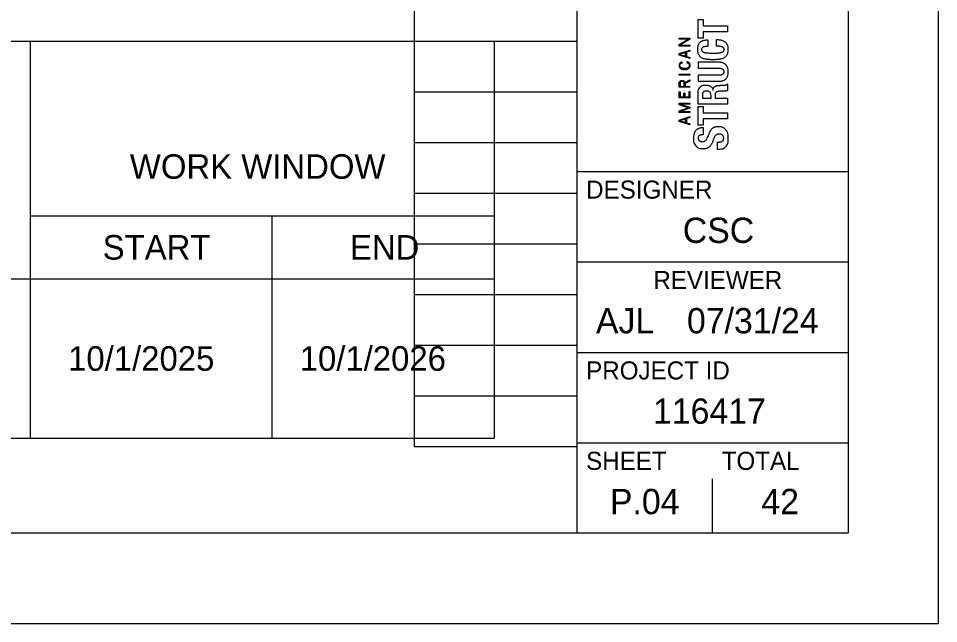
# Model space of a CAD drawing. Extents: x 0 to 84.3, y -13.4 to 22.
# Drawn here: x 28.91 to 34, y 0 to 3.35 of the extents above; entities that cross this region are included whole.
import ezdxf

# ---------------------------------------------------------------- set-up
doc = ezdxf.new("R2010")
doc.units = 0
for name, color, linetype in [('SH_Border', 7, 'Continuous'), ('SH_Cut_Line', 7, 'Continuous'), ('SH_Data', 7, 'Continuous'), ('SH_Text', 7, 'Continuous')]:
    doc.layers.add(name, color=color, linetype=linetype)

msp = doc.modelspace()

# ---------------------------------------------------------------- linework, layer by layer
at = {"layer": 'SH_Border'}
for p, q in [((32, 0.5), (32, 21.5)), ((32, 2.5), (33.5, 2.5)), ((32, 2), (33.5, 2)), ((32, 1.5), (33.5, 1.5)), ((32, 1), (33.5, 1))]:
    msp.add_line(p, q, dxfattribs=at)
msp.add_lwpolyline([(1.5, 21.5), (33.5, 21.5), (33.5, 0.5), (1.5, 0.5)], close=True, dxfattribs=at)
at = {"layer": 'SH_Cut_Line'}
msp.add_lwpolyline([(0, 0), (34, 0), (34, 22), (0, 22)], close=True, dxfattribs=at)
at = {"layer": 'SH_Data'}
for p, q in [((31.1, 0.98), (31.1, 21.14)), ((32, 0.98), (32, 21.14)), ((31.1, 3.22), (32, 3.22)), ((31.1, 2.94), (32, 2.94)), ((31.1, 2.66), (32, 2.66)), ((31.1, 2.38), (32, 2.38)), ((31.1, 2.1), (32, 2.1)), ((31.1, 1.82), (32, 1.82)), ((31.1, 1.54), (32, 1.54)), ((31.1, 1.26), (32, 1.26)), ((31.1, 0.98), (32, 0.98)), ((32.75, 0.5), (32.75, 0.8)), ((32.375, 0.675), (32.375, 0.675))]:
    msp.add_line(p, q, dxfattribs=at)
for points in [[(32.6696, 3.3411), (32.6967, 3.3411), (32.6967, 3.3054), (32.8329, 3.3054), (32.8329, 3.2726), (32.6967, 3.2726), (32.6967, 3.2369), (32.6696, 3.2369), (32.6696, 3.3411)], [(32.565, 3.1938), (32.565, 3.2029), (32.6146, 3.2313), (32.6146, 3.2315), (32.565, 3.2315), (32.565, 3.2369), (32.6245, 3.2369), (32.6245, 3.2313), (32.5694, 3.1994), (32.5694, 3.1992), (32.6245, 3.1992), (32.6245, 3.1938), (32.565, 3.1938)], [(32.6245, 3.1249), (32.565, 3.1439), (32.565, 3.1523), (32.6245, 3.1711), (32.6245, 3.1653), (32.605, 3.1593), (32.605, 3.1368), (32.6245, 3.1307), (32.6245, 3.1249)], [(32.6006, 3.1382), (32.6006, 3.158), (32.5694, 3.1481), (32.5694, 3.148), (32.6006, 3.1382)], [(32.565, 3.0336), (32.565, 3.039), (32.6245, 3.039), (32.6245, 3.0336), (32.565, 3.0336)], [(32.5963, 2.9917), (32.6245, 3.0063), (32.6245, 3.0004), (32.5973, 2.9865), (32.5973, 2.9711), (32.6245, 2.9711), (32.6245, 2.9656), (32.565, 2.9656), (32.565, 2.9858)], [(32.5694, 2.9711), (32.5928, 2.9711), (32.5928, 2.9858)], [(32.5694, 2.9858), (32.5694, 2.9711)], [(32.8316, 2.9843), (32.8329, 2.9843), (32.8329, 2.9486)], [(32.6245, 2.9074), (32.565, 2.9074), (32.565, 2.9414), (32.5694, 2.9414), (32.5694, 2.9129), (32.5913, 2.9129), (32.5913, 2.9334), (32.5958, 2.9334), (32.5958, 2.9129), (32.62, 2.9129), (32.62, 2.943), (32.6245, 2.943), (32.6245, 2.9074)], [(32.8329, 2.8731), (32.6696, 2.8731), (32.6696, 2.9341)], [(32.694, 2.9217), (32.694, 2.9059)], [(32.694, 2.9059), (32.7409, 2.9059), (32.7409, 2.9198)], [(32.7519, 2.9506), (32.7524, 2.9506)], [(32.7638, 2.9238), (32.7638, 2.9059), (32.8329, 2.9059), (32.8329, 2.8731)], [(32.8158, 2.9445), (32.7844, 2.9435)], [(32.6245, 2.8264), (32.565, 2.8264), (32.565, 2.836), (32.6154, 2.8524), (32.6154, 2.8526), (32.565, 2.8691), (32.565, 2.8787), (32.6245, 2.8787), (32.6245, 2.8732), (32.5694, 2.8732), (32.5694, 2.8731), (32.6245, 2.8551), (32.6245, 2.8499), (32.5694, 2.832), (32.5694, 2.8318), (32.6245, 2.8318), (32.6245, 2.8264)], [(32.6696, 2.86), (32.6967, 2.86), (32.6967, 2.8242), (32.8329, 2.8242), (32.8329, 2.7914), (32.6967, 2.7914), (32.6967, 2.7557), (32.6696, 2.7557), (32.6696, 2.86)], [(32.6245, 2.7575), (32.565, 2.7766), (32.565, 2.7849), (32.6245, 2.8037), (32.6245, 2.7979), (32.605, 2.7919), (32.605, 2.7694), (32.6245, 2.7633), (32.6245, 2.7575)], [(32.6006, 2.7708), (32.6006, 2.7906), (32.5694, 2.7808), (32.5694, 2.7806), (32.6006, 2.7708)]]:
    msp.add_lwpolyline(points, dxfattribs=at)
for points in [[(32.7247, 3.1935), (32.7128, 3.1935), (32.7041, 3.1921), (32.6987, 3.1892), (32.6933, 3.1864), (32.6906, 3.1812), (32.6906, 3.1737), (32.6906, 3.1696), (32.6917, 3.1662), (32.6939, 3.1635), (32.6961, 3.1608), (32.6997, 3.1587), (32.7046, 3.1572), (32.7095, 3.1556), (32.716, 3.1546), (32.724, 3.154), (32.732, 3.1533), (32.7418, 3.153), (32.7533, 3.153), (32.7657, 3.153), (32.7756, 3.1535), (32.7832, 3.1543), (32.7909, 3.1551), (32.7968, 3.1565), (32.8009, 3.1582), (32.8051, 3.16), (32.8079, 3.1622), (32.8094, 3.1649), (32.8108, 3.1676), (32.8116, 3.1707), (32.8116, 3.1743), (32.8116, 3.1772), (32.8111, 3.1799), (32.8101, 3.1824), (32.8091, 3.185), (32.8071, 3.1872), (32.8041, 3.189), (32.8011, 3.1909), (32.7969, 3.1923), (32.7915, 3.1934), (32.7861, 3.1945), (32.779, 3.195), (32.7701, 3.195), (32.7701, 3.195), (32.7701, 3.2279), (32.7701, 3.2279), (32.779, 3.2279), (32.7874, 3.2272), (32.7953, 3.2258), (32.8032, 3.2244), (32.8102, 3.2219), (32.8163, 3.2181), (32.8224, 3.2144), (32.8272, 3.2091), (32.8307, 3.2023), (32.8342, 3.1955), (32.836, 3.1867), (32.836, 3.1759), (32.836, 3.1635), (32.8339, 3.1536), (32.8297, 3.1463), (32.8255, 3.139), (32.8197, 3.1334), (32.8122, 3.1295), (32.8047, 3.1256), (32.7957, 3.1231), (32.7853, 3.1219), (32.7748, 3.1208), (32.7634, 3.1202), (32.7511, 3.1202), (32.7387, 3.1202), (32.7273, 3.1208), (32.7168, 3.1219), (32.7064, 3.1231), (32.6974, 3.1256), (32.6899, 3.1295), (32.6825, 3.1334), (32.6766, 3.139), (32.6724, 3.1463), (32.6682, 3.1536), (32.6661, 3.1634), (32.6661, 3.1758), (32.6661, 3.1875), (32.6681, 3.1968), (32.6719, 3.2036), (32.6757, 3.2104), (32.6806, 3.2154), (32.6865, 3.2188), (32.6924, 3.2221), (32.6988, 3.2242), (32.7056, 3.2251), (32.7124, 3.2259), (32.7187, 3.2263), (32.7247, 3.2263), (32.7247, 3.2263), (32.7247, 3.1935), (32.7247, 3.1935)], [(32.5824, 3.1009), (32.5781, 3.0997), (32.5747, 3.0978), (32.5723, 3.0954), (32.5699, 3.0931), (32.5687, 3.09), (32.5687, 3.0864), (32.5687, 3.0835), (32.5694, 3.0809), (32.5707, 3.0788), (32.572, 3.0767), (32.5739, 3.0749), (32.5763, 3.0735), (32.5786, 3.0721), (32.5814, 3.0711), (32.5846, 3.0704), (32.5878, 3.0698), (32.5912, 3.0694), (32.5948, 3.0694), (32.5984, 3.0694), (32.6018, 3.0698), (32.605, 3.0704), (32.6082, 3.0711), (32.6109, 3.0721), (32.6133, 3.0736), (32.6157, 3.075), (32.6175, 3.0768), (32.6189, 3.079), (32.6202, 3.0813), (32.6209, 3.0839), (32.6209, 3.087), (32.6209, 3.0894), (32.6205, 3.0914), (32.6197, 3.0931), (32.6189, 3.0947), (32.6178, 3.0961), (32.6165, 3.0973), (32.6152, 3.0985), (32.6137, 3.0994), (32.6119, 3.1001), (32.6101, 3.1009), (32.6083, 3.1015), (32.6064, 3.102), (32.6064, 3.102), (32.6073, 3.1071), (32.6073, 3.1071), (32.6099, 3.1066), (32.6124, 3.1058), (32.6146, 3.1048), (32.6168, 3.1037), (32.6187, 3.1024), (32.6203, 3.1008), (32.6219, 3.0992), (32.6232, 3.0973), (32.624, 3.095), (32.6249, 3.0927), (32.6254, 3.09), (32.6254, 3.0869), (32.6254, 3.0833), (32.6246, 3.0801), (32.6232, 3.0772), (32.6217, 3.0744), (32.6197, 3.072), (32.617, 3.0701), (32.6143, 3.0681), (32.611, 3.0666), (32.6073, 3.0656), (32.6036, 3.0645), (32.5994, 3.064), (32.5948, 3.064), (32.5902, 3.064), (32.586, 3.0645), (32.5823, 3.0656), (32.5785, 3.0666), (32.5753, 3.0681), (32.5726, 3.0701), (32.5699, 3.072), (32.5678, 3.0744), (32.5664, 3.0772), (32.5649, 3.0801), (32.5642, 3.0833), (32.5642, 3.0869), (32.5642, 3.0895), (32.5646, 3.0919), (32.5655, 3.094), (32.5664, 3.0961), (32.5676, 3.0979), (32.5691, 3.0995), (32.5707, 3.1011), (32.5725, 3.1024), (32.5746, 3.1034), (32.5767, 3.1044), (32.579, 3.1053), (32.5814, 3.106), (32.5814, 3.106), (32.5824, 3.1009), (32.5824, 3.1009)], [(32.6696, 3.0325), (32.6696, 3.0325), (32.7832, 3.0325), (32.7832, 3.0325), (32.7874, 3.0325), (32.7911, 3.0328), (32.7946, 3.0333), (32.798, 3.0338), (32.8009, 3.0348), (32.8035, 3.0363), (32.806, 3.0377), (32.8079, 3.0397), (32.8094, 3.0422), (32.8108, 3.0448), (32.8116, 3.0479), (32.8116, 3.0518), (32.8116, 3.0556), (32.8108, 3.0588), (32.8094, 3.0613), (32.8079, 3.0638), (32.806, 3.0658), (32.8035, 3.0673), (32.8009, 3.0687), (32.798, 3.0697), (32.7946, 3.0702), (32.7911, 3.0708), (32.7874, 3.071), (32.7832, 3.071), (32.7832, 3.071), (32.6696, 3.071), (32.6696, 3.071), (32.6696, 3.071), (32.6696, 3.1039), (32.6696, 3.1039), (32.6696, 3.1039), (32.7834, 3.1039), (32.7834, 3.1039), (32.7938, 3.1039), (32.8023, 3.1024), (32.8091, 3.0995), (32.8159, 3.0966), (32.8213, 3.0928), (32.8252, 3.0879), (32.8292, 3.083), (32.832, 3.0774), (32.8336, 3.0712), (32.8352, 3.0649), (32.836, 3.0585), (32.836, 3.0518), (32.836, 3.0451), (32.8353, 3.0386), (32.8339, 3.0323), (32.8326, 3.0261), (32.8299, 3.0205), (32.826, 3.0157), (32.8222, 3.0108), (32.8168, 3.0069), (32.81, 3.004), (32.8033, 3.0011), (32.7944, 2.9997), (32.7834, 2.9997), (32.7834, 2.9997), (32.6696, 2.9997), (32.6696, 2.9997), (32.6696, 2.9997), (32.6696, 3.0325), (32.6696, 3.0325)], [(32.565, 2.9858), (32.565, 2.9917), (32.5664, 2.9962), (32.5694, 2.9994), (32.5723, 3.0025), (32.5762, 3.0041), (32.5811, 3.0041), (32.5851, 3.0041), (32.5883, 3.0031), (32.5909, 3.0011), (32.5934, 2.9991), (32.5952, 2.996), (32.5963, 2.9917)], [(32.5928, 2.9858), (32.5928, 2.9897), (32.5918, 2.9929), (32.5897, 2.9952), (32.5877, 2.9975), (32.5848, 2.9987), (32.5811, 2.9987), (32.5775, 2.9987), (32.5746, 2.9976), (32.5725, 2.9954), (32.5705, 2.9933), (32.5694, 2.9901), (32.5694, 2.9858)], [(32.6696, 2.9341), (32.6696, 2.9477), (32.6731, 2.9584), (32.6801, 2.9661), (32.6871, 2.9738), (32.6976, 2.9777), (32.7117, 2.9777), (32.7227, 2.9777), (32.7316, 2.9755), (32.7386, 2.9711), (32.7455, 2.9667), (32.75, 2.9598), (32.7519, 2.9506)], [(32.7524, 2.9506), (32.7532, 2.9562), (32.7546, 2.9607), (32.7566, 2.9641), (32.7587, 2.9674), (32.7617, 2.9701), (32.7655, 2.972), (32.7694, 2.9739), (32.7744, 2.9752), (32.7803, 2.9758), (32.7863, 2.9764), (32.7936, 2.9768), (32.8023, 2.9769), (32.811, 2.9771), (32.8176, 2.9776), (32.8222, 2.9784), (32.8268, 2.9793), (32.8299, 2.9812), (32.8316, 2.9843)], [(32.7409, 2.9198), (32.7409, 2.9279), (32.7391, 2.934), (32.7354, 2.9384), (32.7316, 2.9427), (32.7254, 2.9449), (32.7166, 2.9449), (32.7015, 2.9449), (32.694, 2.9371), (32.694, 2.9217)], [(32.7844, 2.9435), (32.778, 2.9432), (32.773, 2.9416), (32.7693, 2.9386), (32.7657, 2.9355), (32.7638, 2.9306), (32.7638, 2.9238)], [(32.8329, 2.9486), (32.8307, 2.9469), (32.828, 2.9458), (32.825, 2.9454), (32.8221, 2.9449), (32.819, 2.9446), (32.8158, 2.9445)], [(32.7753, 2.6613), (32.7753, 2.6613), (32.7807, 2.6613), (32.7807, 2.6613), (32.785, 2.6613), (32.789, 2.6616), (32.7925, 2.6623), (32.7961, 2.663), (32.7991, 2.6643), (32.8015, 2.6662), (32.8039, 2.6681), (32.8058, 2.6706), (32.8072, 2.6737), (32.8086, 2.6769), (32.8093, 2.6809), (32.8093, 2.6859), (32.8093, 2.6916), (32.8074, 2.6968), (32.8037, 2.7014), (32.8, 2.7059), (32.7942, 2.7082), (32.7864, 2.7082), (32.7822, 2.7082), (32.7787, 2.7077), (32.7756, 2.7066), (32.7726, 2.7054), (32.7699, 2.7036), (32.7674, 2.701), (32.765, 2.6984), (32.7628, 2.695), (32.7608, 2.6907), (32.7588, 2.6865), (32.7568, 2.6813), (32.7547, 2.6751), (32.7519, 2.6667), (32.7489, 2.6596), (32.7455, 2.6535), (32.7421, 2.6475), (32.7382, 2.6424), (32.7339, 2.6384), (32.7296, 2.6343), (32.7246, 2.6313), (32.7188, 2.6294), (32.7131, 2.6275), (32.7064, 2.6266), (32.6986, 2.6266), (32.6804, 2.6266), (32.6667, 2.6316), (32.6576, 2.6418), (32.6485, 2.652), (32.644, 2.666), (32.644, 2.6838), (32.644, 2.6921), (32.6449, 2.6997), (32.6467, 2.7067), (32.6485, 2.7137), (32.6515, 2.7198), (32.6555, 2.7249), (32.6596, 2.73), (32.6648, 2.7339), (32.6711, 2.7368), (32.6774, 2.7396), (32.685, 2.7411), (32.6938, 2.7411), (32.6938, 2.7411), (32.699, 2.7411), (32.699, 2.7411), (32.699, 2.7411), (32.699, 2.7052), (32.699, 2.7052), (32.6902, 2.7052), (32.6834, 2.7036), (32.6786, 2.7005), (32.6739, 2.6975), (32.6715, 2.6923), (32.6715, 2.6851), (32.6715, 2.681), (32.6721, 2.6775), (32.6733, 2.6748), (32.6745, 2.672), (32.6761, 2.6698), (32.6781, 2.6682), (32.6801, 2.6666), (32.6824, 2.6655), (32.685, 2.6649), (32.6876, 2.6643), (32.6903, 2.664), (32.6931, 2.664), (32.6988, 2.664), (32.7036, 2.6652), (32.7075, 2.6676), (32.7114, 2.67), (32.715, 2.6752), (32.7183, 2.6831), (32.7183, 2.6831), (32.7307, 2.7119), (32.7307, 2.7119), (32.7338, 2.7188), (32.7371, 2.7246), (32.7405, 2.7292), (32.7438, 2.7337), (32.7475, 2.7374), (32.7514, 2.74), (32.7553, 2.7427), (32.7596, 2.7446), (32.7643, 2.7456), (32.7689, 2.7467), (32.7741, 2.7472), (32.7798, 2.7472), (32.7994, 2.7472), (32.8138, 2.7415), (32.823, 2.7302), (32.8322, 2.7188), (32.8367, 2.703), (32.8367, 2.6828), (32.8367, 2.6617), (32.832, 2.6466), (32.8226, 2.6375), (32.8132, 2.6284), (32.7999, 2.6239), (32.7828, 2.6239), (32.7828, 2.6239), (32.7753, 2.6239), (32.7753, 2.6239), (32.7753, 2.6239), (32.7753, 2.6613), (32.7753, 2.6613)]]:
    msp.add_open_spline(points, degree=3, dxfattribs=at)
at = {"layer": 'SH_Text'}
for p, q in [((24.66, 3.22), (31.5436, 3.22)), ((28.9758, 1.0259), (28.9758, 3.22)), ((31.5436, 1.0259), (31.5436, 3.22)), ((28.9758, 2.2556), (31.5436, 2.2556)), ((30.314, 1.0259), (30.314, 2.2556)), ((24.66, 1.906), (31.5436, 1.906)), ((24.66, 1.0259), (31.5436, 1.0259))]:
    msp.add_line(p, q, dxfattribs=at)

# ---------------------------------------------------------------- texts
at = {"layer": 'SH_Data'}
for s, height, p in [('DESIGNER', 0.1, (32.05, 2.35)), ('CSC', 0.14, (32.5847, 2.105)), ('REVIEWER', 0.1, (32.4218, 1.85)), ('AJL', 0.14, (32.1043, 1.605)), ('07/31/24', 0.14, (32.6078, 1.605)), ('PROJECT ID', 0.1, (32.05, 1.35)), ('116417', 0.14, (32.4198, 1.105)), ('SHEET', 0.1, (32.05, 0.85)), ('TOTAL', 0.1, (32.8, 0.85)), ('P.04', 0.14, (32.1816, 0.605)), ('42', 0.14, (33.0194, 0.605))]:
    msp.add_text(s, height=height, dxfattribs=at).set_placement(p)
at = {"layer": 'SH_Text'}
for s, p in [('WORK', (29.5258, 2.4596)), (' WINDOW', (30.0916, 2.4596)), ('START', (29.3756, 2.0128)), ('END', (30.7436, 2.0128)), ('10/1/2025', (29.1841, 1.3979)), ('10/1/2026', (30.4654, 1.3979))]:
    msp.add_text(s, height=0.13601, dxfattribs=at).set_placement(p)

doc.saveas('drawing.dxf')
